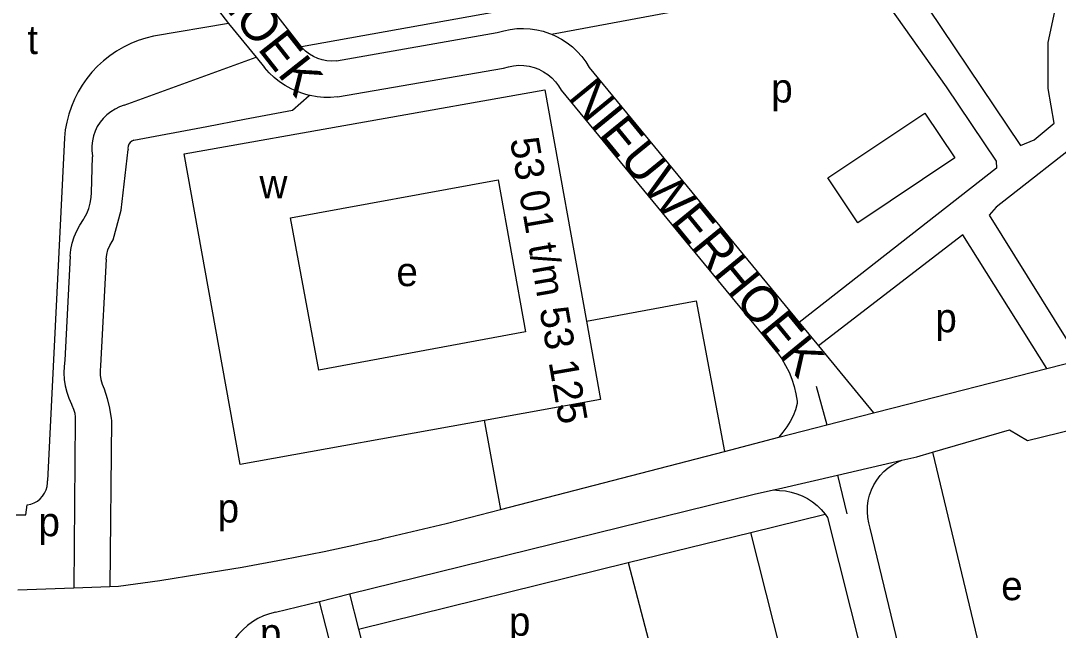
# Model space of a CAD drawing. Extents: x 157794 to 159375, y 380877 to 382306.
# Drawn here: x 158508.3 to 158651.8, y 381260.8 to 381345.1 of the extents above; entities that cross this region are included whole.
import ezdxf

# ---------------------------------------------------------------- set-up
doc = ezdxf.new("R2010")
doc.units = 0
for name, color, linetype in [('BLT_Basislijn', 7, 'Continuous'), ('BLT_Bebouwing', 7, 'Continuous'), ('BLT_Centroide', 7, 'Continuous'), ('BLT_Huisnummer_reeks', 7, 'Continuous'), ('BLT_Straatnaam', 7, 'Continuous')]:
    doc.layers.add(name, color=color, linetype=linetype)

msp = doc.modelspace()

# ---------------------------------------------------------------- linework, layer by layer
at = {"layer": 'BLT_Basislijn'}
for p, q in [((158531.45, 381352), (158537.03, 381344.71)), ((158547.12, 381341.48), (158543.6, 381346.05)), ((158537.03, 381344.71), (158526.68, 381342.96)), ((158537.03, 381344.71), (158540.88, 381340.03)), ((158551.96, 381339.56), (158574.22, 381343.45)), ((158522.62, 381333.39), (158540.88, 381340.03)), ((158540.88, 381340.03), (158542.02, 381338.64)), ((158552.1, 381334.57), (158575.07, 381338.52)), ((158586.94, 381338.62), (158615.98, 381303.36)), ((158583.07, 381335.47), (158612.29, 381299.98)), ((158534.02, 381330.47), (158539.26, 381331.46)), ((158619.96, 381323.34), (158633.35, 381332.32)), ((158633.35, 381332.32), (158637.49, 381326.14)), ((158523.93, 381328.56), (158534.02, 381330.47)), ((158514.33, 381328.88), (158511.99, 381281.44)), ((158522.17, 381318.87), (158523.14, 381327.28)), ((158518.1, 381321.34), (158518.24, 381326.28)), ((158637.49, 381326.14), (158624.11, 381317.16)), ((158624.11, 381317.16), (158619.96, 381323.34)), ((158521.1, 381314.8), (158522.17, 381318.87)), ((158515.11, 381312.54), (158514.4, 381298.16)), ((158520.09, 381312.11), (158519.33, 381297.34)), ((158615.98, 381303.36), (158618.64, 381300.13)), ((158618.64, 381300.13), (158626.26, 381290.87)), ((158650.24, 381297.01), (158654.74, 381298.16)), ((158628.97, 381291.57), (158650.24, 381297.01)), ((158618.35, 381294.55), (158619.82, 381289.2)), ((158626.26, 381290.87), (158628.97, 381291.57)), ((158515.84, 381289.87), (158515.62, 381266.66)), ((158520.84, 381289.82), (158520.62, 381266.83)), ((158572.42, 381289.84), (158574.65, 381277.48)), ((158619.82, 381289.2), (158626.26, 381290.87)), ((158613.14, 381287.47), (158619.82, 381289.2)), ((158605.63, 381285.52), (158613.14, 381287.47)), ((158574.65, 381277.48), (158605.63, 381285.52)), ((158632.25, 381284.79), (158634.44, 381285.42)), ((158634.44, 381285.42), (158647.67, 381230.21)), ((158621.27, 381282.25), (158630.19, 381284.31)), ((158630.19, 381284.31), (158632.25, 381284.79)), ((158613.12, 381280.36), (158621.27, 381282.25)), ((158621.27, 381282.25), (158622.55, 381276.88)), ((158553.79, 381265.8), (158609.76, 381279.59)), ((158609.76, 381279.59), (158612.43, 381280.21)), ((158612.43, 381280.21), (158613.12, 381280.36)), ((158568.96, 381276.01), (158574.65, 381277.48)), ((158609.28, 381274.32), (158619.55, 381276.85)), ((158619.55, 381276.85), (158619.89, 381276.38)), ((158619.89, 381276.38), (158628.04, 381243.99)), ((158592.31, 381270.14), (158609.28, 381274.32)), ((158618.09, 381239.58), (158609.28, 381274.32)), ((158637.24, 381227.59), (158625.82, 381274.9)), ((158555.03, 381260.95), (158592.31, 381270.14)), ((158592.31, 381270.14), (158595.12, 381259.43)), ((158515.62, 381266.66), (158520.62, 381266.83)), ((158520.62, 381266.83), (158521.8, 381266.87)), ((158549.61, 381264.77), (158553.79, 381265.8)), ((158553.79, 381265.8), (158555.03, 381260.95)), ((158543.55, 381263.28), (158549.61, 381264.77)), ((158551.39, 381257.96), (158549.61, 381264.77)), ((158555.03, 381260.95), (158557.33, 381252.03))]:
    msp.add_line(p, q, dxfattribs=at)
for points in [[(158731.89, 381437.96), (158745.99, 381415.56), (158754.2, 381384.48), (158754.07, 381380.8), (158752.23, 381379.3), (158750.76, 381379.18), (158735.9, 381381.6), (158689.67, 381369.9), (158688.01, 381367.9), (158680.38, 381366.01), (158668.53, 381362.54), (158628.16, 381356.06), (158547.12, 381341.48)], [(158761.2, 381355.86), (158755.95, 381374.31), (158750.51, 381375.41), (158735.81, 381377.94), (158691.49, 381366.65), (158689.35, 381364.33), (158665.17, 381357.65), (158661.41, 381355.36), (158658.39, 381352.34), (158656.15, 381349.02), (158654.19, 381344.38), (158653.85, 381341.11), (158654.06, 381335.73), (158656.18, 381329.45), (158643.25, 381319.31), (158642.26, 381318.19), (158654.74, 381298.16)], [(158657.5, 381356.32), (158630.22, 381352.22), (158646.6, 381327.82), (158648.47, 381328.62), (158651.27, 381330.92), (158650.42, 381335.7), (158650.42, 381342.06), (158651.48, 381346.99), (158653.39, 381351.38), (158656.74, 381355.68), (158657.5, 381356.32)], [(158581.73, 381343.22), (158624.92, 381351.29), (158625.62, 381351.08), (158636.33, 381335.94)], [(158526.68, 381342.96), (158525.6, 381342.69), (158524.53, 381342.35), (158523.5, 381341.93), (158522.5, 381341.43), (158521.53, 381340.87), (158520.61, 381340.24), (158519.74, 381339.54), (158518.92, 381338.79), (158518.15, 381337.97), (158517.45, 381337.11), (158516.81, 381336.2), (158516.23, 381335.24), (158515.73, 381334.24), (158515.3, 381333.21), (158514.94, 381332.15), (158514.66, 381331.07), (158514.46, 381329.98), (158514.33, 381328.88)], [(158574.22, 381343.45), (158575.1, 381343.71), (158576.01, 381343.89), (158576.92, 381344), (158577.85, 381344.03), (158578.77, 381343.97), (158579.68, 381343.84), (158580.58, 381343.63), (158581.45, 381343.34), (158581.73, 381343.22)], [(158581.73, 381343.22), (158582.3, 381342.97), (158583.11, 381342.54), (158583.88, 381342.03), (158584.61, 381341.46), (158585.28, 381340.83), (158585.9, 381340.15), (158586.45, 381339.41), (158586.94, 381338.62)], [(158551.96, 381339.56), (158551.31, 381339.52), (158550.65, 381339.55), (158550.01, 381339.67), (158549.38, 381339.86), (158548.78, 381340.13), (158548.22, 381340.47), (158547.7, 381340.88), (158547.24, 381341.34), (158547.12, 381341.48)], [(158548.21, 381334.76), (158547.44, 381334.96), (158546.55, 381335.28), (158545.69, 381335.67), (158544.87, 381336.12), (158544.09, 381336.65), (158543.35, 381337.24), (158542.67, 381337.9), (158542.02, 381338.64)], [(158575.07, 381338.52), (158575.75, 381338.73), (158576.46, 381338.87), (158577.18, 381338.93), (158577.9, 381338.91), (158578.61, 381338.8), (158579.31, 381338.62), (158579.98, 381338.37), (158580.62, 381338.04), (158581.22, 381337.64), (158581.77, 381337.18), (158582.26, 381336.66), (158582.7, 381336.09), (158583.07, 381335.47)], [(158636.33, 381335.94), (158643.21, 381325.67), (158643.27, 381324.72), (158615.98, 381303.36)], [(158539.26, 381331.46), (158545.88, 381332.71), (158548.21, 381334.76)], [(158552.1, 381334.57), (158551.16, 381334.49), (158550.22, 381334.49), (158549.28, 381334.57), (158548.35, 381334.73), (158548.21, 381334.76)], [(158522.62, 381333.39), (158521.97, 381333.17), (158521.34, 381332.88), (158520.74, 381332.51), (158520.19, 381332.08), (158519.69, 381331.59), (158519.26, 381331.04), (158518.88, 381330.45), (158518.58, 381329.82), (158518.35, 381329.16), (158518.2, 381328.48), (158518.12, 381327.79), (158518.13, 381327.09), (158518.22, 381326.4), (158518.24, 381326.28)], [(158523.93, 381328.56), (158523.66, 381328.45), (158523.43, 381328.27), (158523.25, 381328.03), (158523.15, 381327.75), (158523.12, 381327.45), (158523.14, 381327.28)], [(158517.07, 381317.76), (158517.43, 381318.43), (158517.71, 381319.14), (158517.92, 381319.88), (158518.05, 381320.64), (158518.1, 381321.34)], [(158515.11, 381312.54), (158515.23, 381313.44), (158515.42, 381314.32), (158515.7, 381315.19), (158516.05, 381316.03), (158516.46, 381316.83), (158516.96, 381317.6), (158517.07, 381317.76)], [(158650.24, 381297.01), (158638.6, 381315.49), (158618.64, 381300.13)], [(158520.09, 381312.11), (158520.19, 381312.76), (158520.36, 381313.39), (158520.61, 381313.99), (158520.93, 381314.55), (158521.1, 381314.8)], [(158586.55, 381303.55), (158601.71, 381306.33), (158605.63, 381285.52)], [(158612.29, 381299.98), (158612.96, 381299.17), (158613.56, 381298.32), (158614.1, 381297.42), (158614.57, 381296.48), (158614.96, 381295.52), (158615.28, 381294.52), (158615.52, 381293.5), (158615.69, 381292.47), (158615.72, 381292.14)], [(158514.4, 381298.16), (158514.29, 381297.27), (158514.26, 381296.38), (158514.31, 381295.48), (158514.45, 381294.6), (158514.66, 381293.73), (158514.94, 381292.88), (158515.31, 381292.06), (158515.38, 381291.91)], [(158519.33, 381297.34), (158519.27, 381296.71), (158519.28, 381296.08), (158519.38, 381295.45), (158519.55, 381294.84), (158519.82, 381294.2)], [(158519.82, 381294.2), (158520.23, 381292.85), (158520.56, 381291.48), (158520.81, 381290.09), (158520.84, 381289.82)], [(158634.44, 381285.42), (158645.09, 381288.49), (158647.56, 381287.01), (158662.63, 381290.72), (158663.37, 381293.19), (158665.84, 381293.93)], [(158515.38, 381291.91), (158515.61, 381291.38), (158515.76, 381290.83), (158515.84, 381290.26), (158515.84, 381289.87)], [(158615.72, 381292.14), (158615.47, 381291.29), (158615.14, 381290.46), (158614.73, 381289.66), (158614.26, 381288.91), (158613.72, 381288.2), (158613.14, 381287.47)], [(158625.82, 381274.9), (158625.61, 381275.64), (158625.47, 381276.4), (158625.42, 381277.17), (158625.44, 381277.95), (158625.54, 381278.71), (158625.72, 381279.46), (158625.98, 381280.19), (158626.31, 381280.89), (158626.71, 381281.55), (158627.18, 381282.17), (158627.71, 381282.73), (158628.29, 381283.24), (158628.93, 381283.68), (158629.6, 381284.05), (158630.19, 381284.31)], [(158509.19, 381278.13), (158509.68, 381278.23), (158510.15, 381278.4), (158510.59, 381278.65), (158510.98, 381278.96), (158511.32, 381279.33), (158511.6, 381279.75), (158511.81, 381280.21), (158511.94, 381280.69), (158511.99, 381281.19), (158511.99, 381281.44)], [(158612.43, 381280.21), (158613.27, 381280.12), (158614.08, 381280.05), (158614.88, 381279.9), (158615.66, 381279.67), (158616.41, 381279.37), (158617.14, 381278.99), (158617.82, 381278.55), (158618.45, 381278.04), (158619.04, 381277.47), (158619.55, 381276.85)], [(158507.67, 381276.75), (158509.02, 381276.75), (158509.19, 381278.13)], [(158558.06, 381273.4), (158558.5, 381273.5), (158567.13, 381275.55), (158568.96, 381276.01)], [(158521.8, 381266.87), (158527.52, 381267.68), (158533.22, 381268.57), (158538.91, 381269.53), (158544.59, 381270.58), (158550.25, 381271.7), (158554.75, 381272.66)], [(158554.75, 381272.66), (158555.89, 381272.91), (158558.06, 381273.4)], [(158507.88, 381266.39), (158515.62, 381266.66)], [(158543.55, 381263.28), (158542.71, 381263.05), (158541.89, 381262.76), (158541.11, 381262.39), (158540.36, 381261.95), (158539.65, 381261.44), (158539, 381260.86), (158538.4, 381260.24), (158537.86, 381259.55), (158537.39, 381258.83), (158536.98, 381258.06), (158536.65, 381257.26), (158536.39, 381256.43), (158536.21, 381255.58), (158536.11, 381254.71), (158536.08, 381253.84), (158536.14, 381252.98), (158536.28, 381252.12), (158536.39, 381251.66)]]:
    msp.add_lwpolyline(points, dxfattribs=at)
at = {"layer": 'BLT_Bebouwing'}
for points in [[(158572.43, 381289.81), (158538.67, 381283.73), (158530.89, 381326.66), (158580.8, 381335.54), (158586.56, 381303.55)], [(158586.56, 381303.55), (158588.51, 381292.71), (158572.43, 381289.81)]]:
    msp.add_lwpolyline(points, dxfattribs=at)
msp.add_lwpolyline([(158545.63, 381317.82), (158574.34, 381323.09), (158578.14, 381302.04), (158549.52, 381296.75)], close=True, dxfattribs=at)

# ---------------------------------------------------------------- texts
at = {"layer": 'BLT_Centroide'}
for s, p in [('t', (158509.21, 381340.48)), ('p', (158612.11, 381333.78)), ('w', (158541.32, 381320.53)), ('e', (158560.26, 381308.38)), ('p', (158634.81, 381302)), ('p', (158535.53, 381275.69)), ('p', (158510.74, 381273.79)), ('e', (158643.92, 381264.94)), ('p', (158575.83, 381260.03)), ('p', (158541.38, 381258.42))]:
    msp.add_text(s, height=4, dxfattribs=at).set_placement(p)
at = {"layer": 'BLT_Huisnummer_reeks'}
msp.add_text('53 01 t/m 53 125', height=4, rotation=279.8731, dxfattribs=at).set_placement((158575.95, 381328.64))
at = {"layer": 'BLT_Straatnaam'}
for height, rotation, p in [(5, 308.2501, (158515.19, 381373.88)), (4.9999, 309.2501, (158583.94, 381334.53))]:
    msp.add_text('NIEUWERHOEK', height=height, rotation=rotation, dxfattribs=at).set_placement(p)

doc.saveas('drawing.dxf')
